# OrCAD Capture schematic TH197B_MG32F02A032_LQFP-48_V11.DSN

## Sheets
1 1. MLink: size B; title: MLink; rev: A; note: MLink
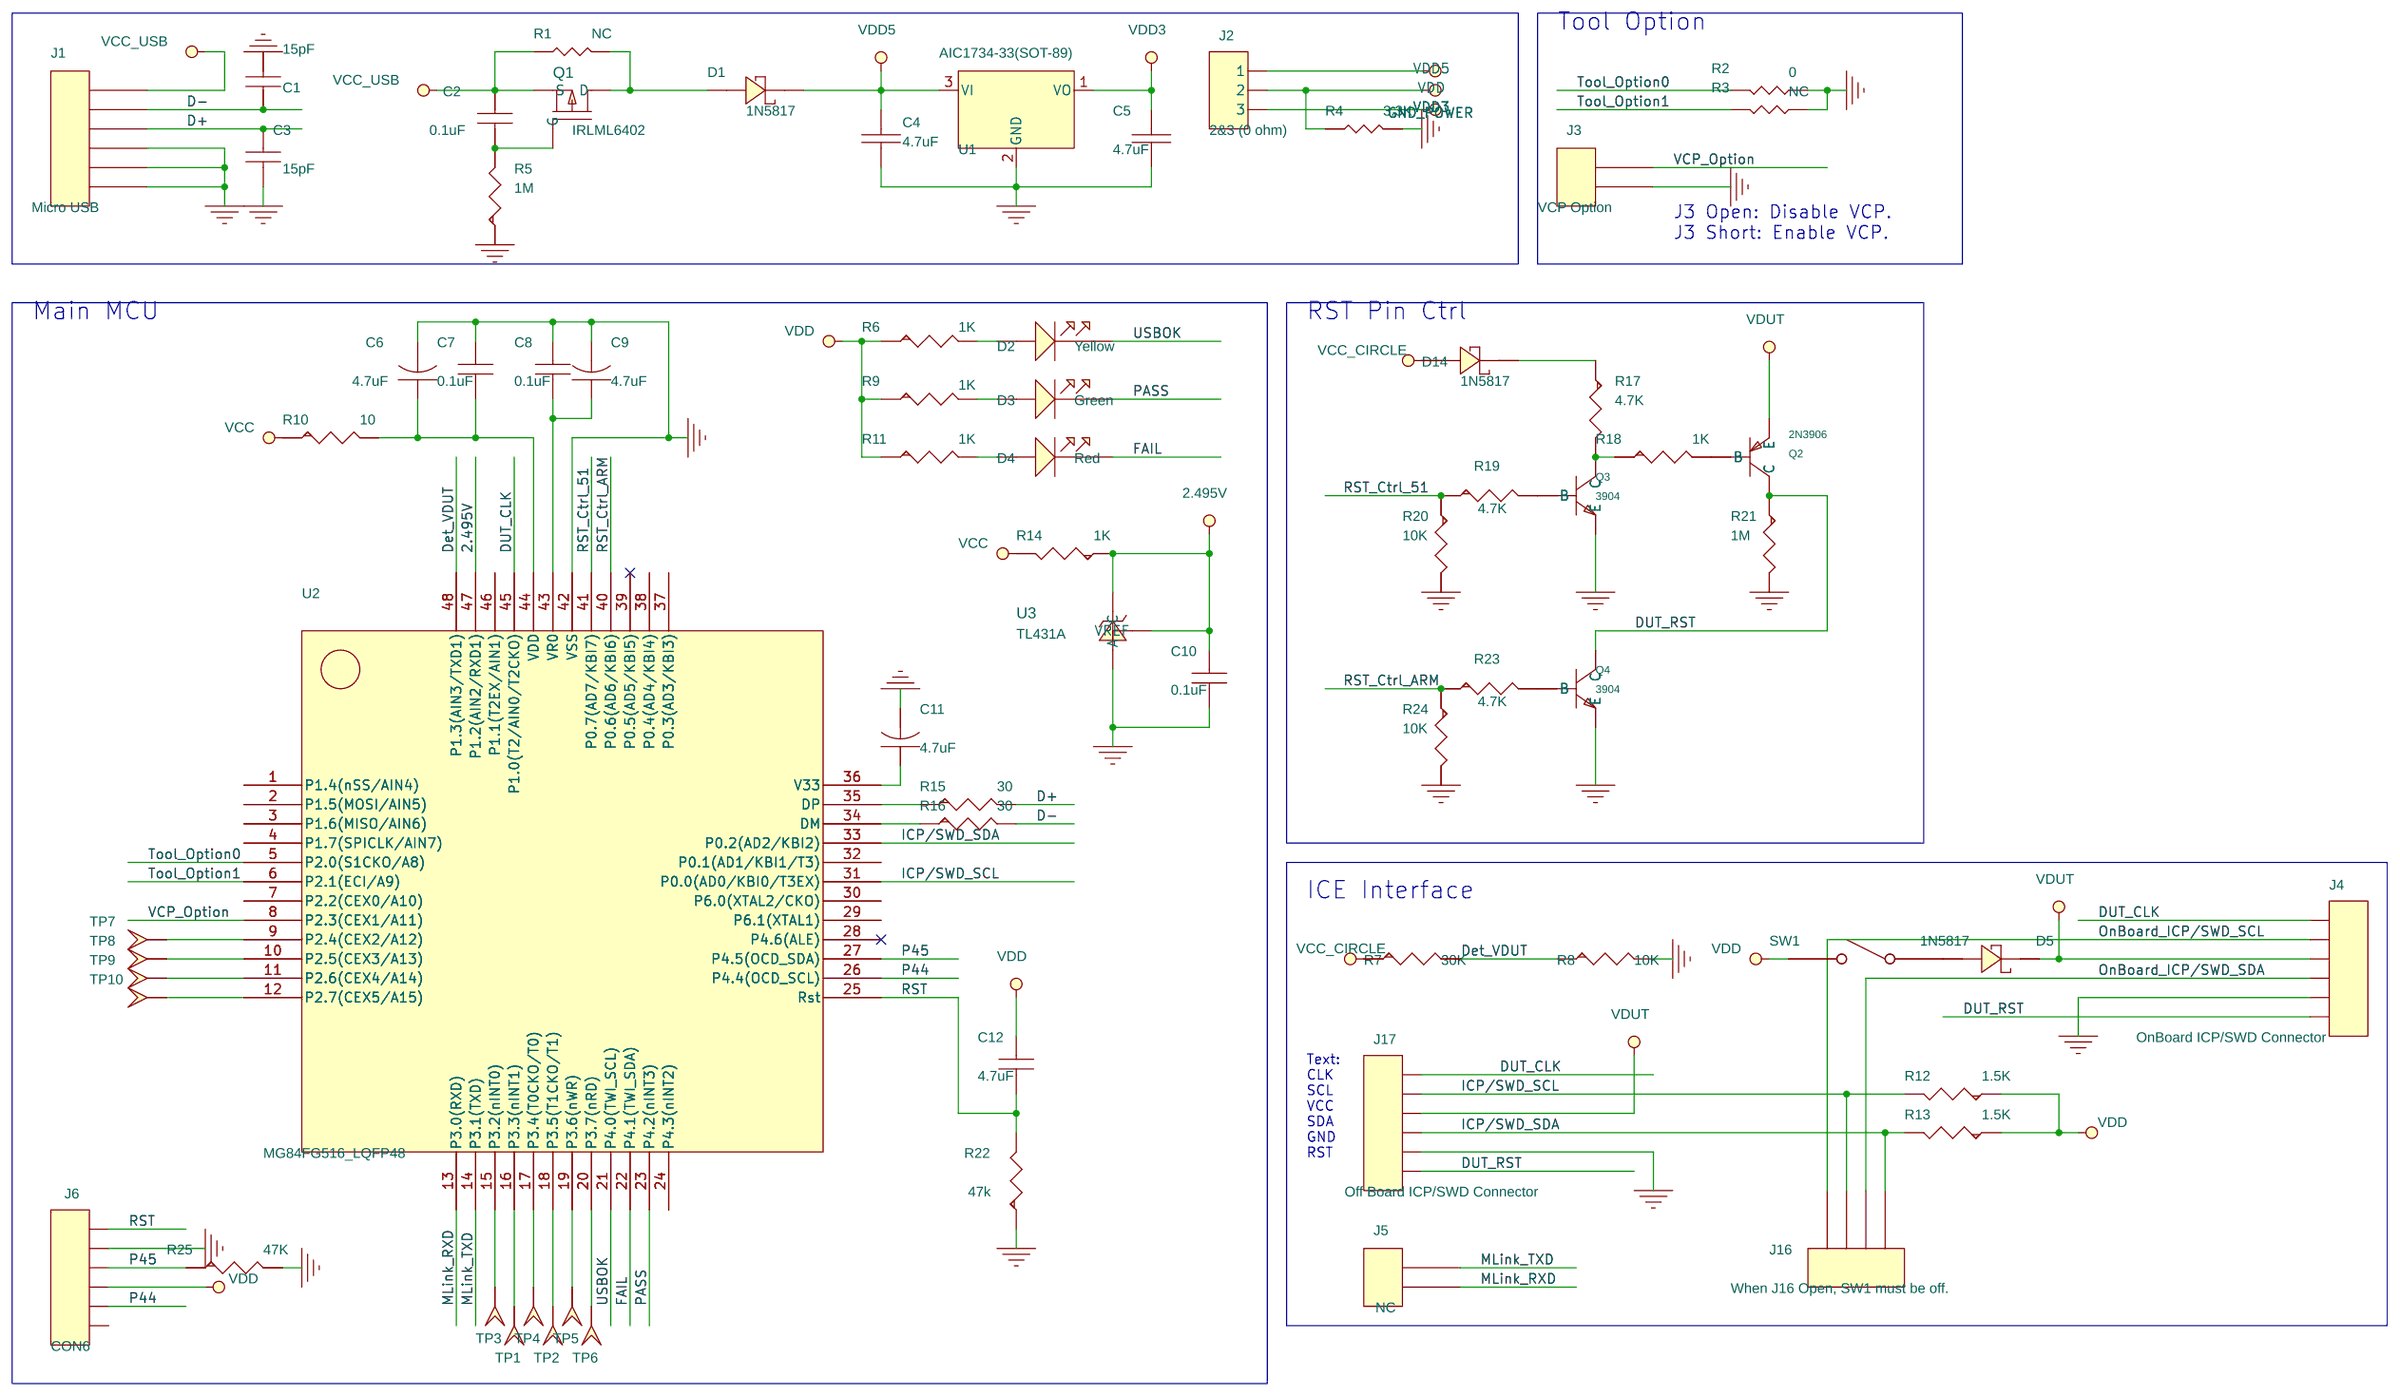
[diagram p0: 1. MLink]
2 2. MG32F02A032: size B; title: MG32F02A032_LQFP-48; note: MG32F02A032_LQFP-48
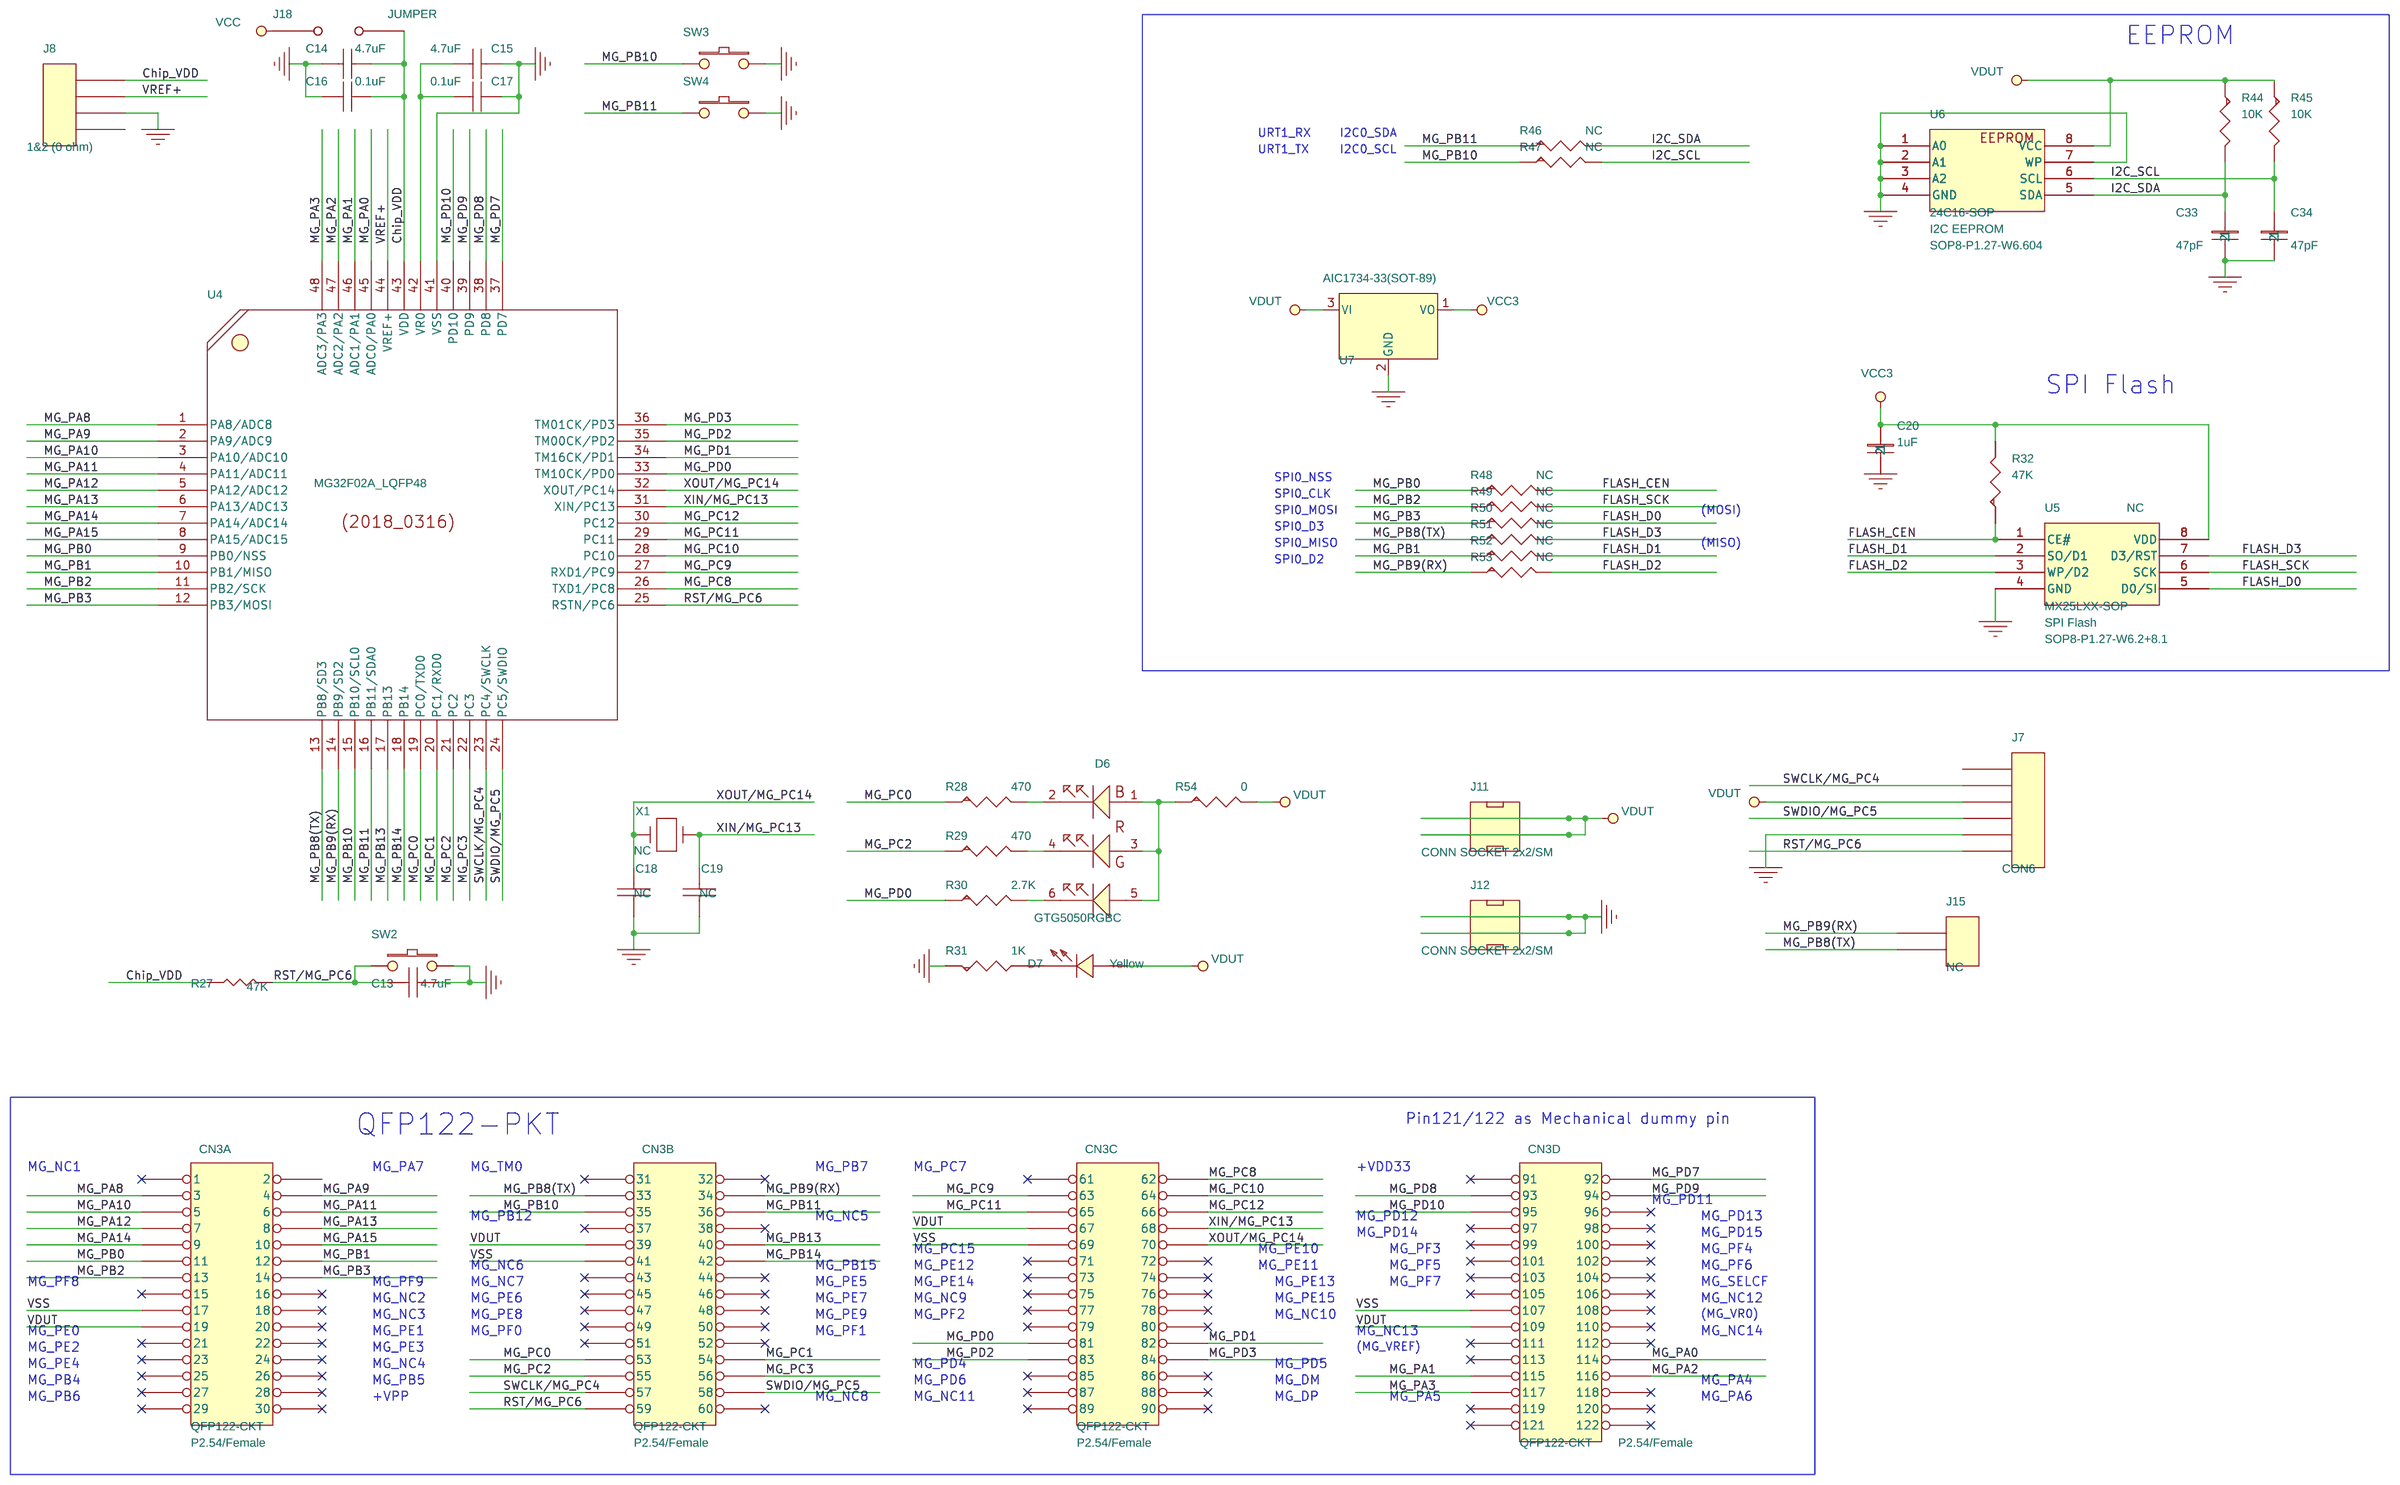
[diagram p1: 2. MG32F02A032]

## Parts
sheet 1. MLink
C1  15pF  [0805C]
C2  0.1uF  [0805C]
C3  15pF  [0805C]
C4  4.7uF  [1206C]
C5  4.7uF  [1206C]
C6  4.7uF  [0805C]
C7  0.1uF  [0805C]
C8  0.1uF  [0805C]
C9  4.7uF  [0805C]
C10  0.1uF  [0805C]
C11  4.7uF
C12  4.7uF  [C0805]
D1  1N5817  [D5817_SMD_1]
D2  Yellow  [0805D]
D3  Green  [0805D]
D4  Red  [0805D]
D5  1N5817  [D5817_SMD_1]
D14  1N5817  [D5817_SMD_1]
J1  Micro USB  [JACK_USB_SMD290X220P065]
J2  2&3 (0 ohm)
J3  VCP Option
J4  OnBoard ICP/SWD Connector
J5  NC
J6  CON6
J16  When J16 Open, SW1 must be off.
J17  Off Board ICP/SWD Connector
Q1  IRLML6402  [SOT23]
Q2  2N3906  [SOT23]
Q3  3904  [SOT23]
Q4  3904  [SOT23]
R1  NC  [0805R]
R2  0  [0805R]
R3  NC  [0805R]
R4  3.3K  [0805R]
R5  1M  [0805R]
R6  1K  [0805R]
R7  30K  [0805R]
R8  10K  [0805R]
R9  1K  [0805R]
R10  10  [0805R]
R11  1K  [0805R]
R12  1.5K  [0805R]
R13  1.5K  [0805R]
R14  1K  [0805R]
R15  30  [0805R]
R16  30  [0805R]
R17  4.7K  [0805R]
R18  1K  [0805R]
R19  4.7K  [0805R]
R20  10K  [0805R]
R21  1M  [0805R]
R22  47k  [0805R]
R23  4.7K  [0805R]
R24  10K  [0805R]
R25  47K  [0805R]
SW1  SW KEY-SPST  [DIP2_SW]
TP1  T POINT A
TP2  T POINT A
TP3  T POINT A
TP4  T POINT A
TP5  T POINT A
TP6  T POINT A
TP7  T POINT A
TP8  T POINT A
TP9  T POINT A
TP10  T POINT A
U1  AIC1734-33(SOT-89)  [SOT89]
U2  MG84FG516_LQFP48
U3  TL431A  [SOT23]
sheet 2. MG32F02A032
C13  4.7uF  [0805C]
C14  4.7uF  [0805C]
C15  4.7uF  [0805C]
C16  0.1uF  [0805C]
C17  0.1uF  [0805C]
C18  NC  [0805C]
C19  NC  [0805C]
C20  1uF  [C-0603]
C33  47pF  [C-0603]
C34  47pF  [C-0603]
CN3  QFP122-CKT  [QFP122-P2.54-CKT]  (sections A,B,C,D)
D6  GTG5050RGBC
D7  Yellow  [0805D]
J7  CON6  [PS6P254F_90]
J8  1&2 (0 ohm)  [PS4P254]
J11  CONN SOCKET 2x2/SM
J12  CONN SOCKET 2x2/SM
J15  NC
J18  JUMPER
R27  47K  [0805R]
R28  470  [0805R]
R29  470  [0805R]
R30  2.7K  [0805R]
R31  1K  [0805R]
R32  47K  [0805R]
R44  10K  [R-0603]
R45  10K  [R-0603]
R46  NC  [0805R]
R47  NC  [0805R]
R48  NC  [0805R]
R49  NC  [0805R]
R50  NC  [0805R]
R51  NC  [0805R]
R52  NC  [0805R]
R53  NC  [0805R]
R54  0  [0805R]
SW2  SW TACT-SPST
SW3  SW TACT-SPST
SW4  SW TACT-SPST
U4  MG32F02A_LQFP48  [LQFP48_7X7_050]
U5  MX25LXX-SOP  [SOP8-P1.27-W6.2+8.1]
U6  24C16-SOP  [SOP8-P1.27-W6.604]
U7  AIC1734-33(SOT-89)  [SOT89]
X1  NC  [X49U]

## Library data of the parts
C1-C3 C7 C8 C10 C12-C17 = CAP_NP
C4 C5 C18 C19 = C_NP
C6 C9 C11 = CAP
D1 D5 D14 = DIODE_SCHOTTKY
D2-D4 = Led0_0
J1 J7 = CON6_v2
J2 = CON3
J3 J5 J15 = CON2
J4 J6 J17 = CON6
J8 J16 = CON4
Q1 = MOSFET_P_GSD
Q2 = PNP_BEC
Q3 Q4 = NPN_BEC
R1-R4 R27 = R_v4
R5-R25 R28-R32 R46-R54 = R
SW1 = SW_KEY-SPST
TP1-TP10 = T_POINT_A
U1 U7 = AIC1722-33
U2 = MG84FG516_LQFP48
U3 = TL431_CYL
C20 = CAP-NP_1
C33 = CAP-NP_2: Package: C0603
C34 = CAP-NP: Package: C0603
CN3 = QFP122-CKT_2: Package: P2.54/Female
D6 = LED_GTG5050RGBC
D7 = LED
J11 J12 = CONN_SOCKET_2x2_SM
J18 = JUMPER
R44 R45 = R: 2ND PART FIELD: SMD_0805
SW2-SW4 = SW_TACT-SPST
U4 = IC-MG32F02A032-LQFP48
U5 = ICM-25LXX: Assembly: NC; Function: SPI Flash
U6 = ICM-24CXX: 1ST PART FIELD: OSD Record Buffer; 2ND PART FIELD: SOP_8PIN; Function: I2C EEPROM
X1 = CRYSTAL

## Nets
2.495V: C10.1 R14.1 U2.47(P1.2(AIN2/RXD1)) U3.1(VREF) U3.2(C)
GND_POWER: C1.2 C3.2 C4.2 C5.2 C6.2 C7.1 C8.1 C9.2 C10.2 C11.2 C13.1 C14.2 C15.2 C16.2 C17.2 C18.2 C19.2 C20.2 C33.2 C34.2 J1.4 J1.5 J1.6 J3.2 J4.5 J6.2 J7.5 J8.3 J12.1 J12.2 J12.3 J12.4 J17.5 Q3.2(E) Q4.2(E) R2.2 R3.2 R4.2 R5.1 R8.2 R20.2 R21.2 R22.1 R24.2 R25.2 R31.1 SW2.2 SW3.2 SW4.2 U1.2(GND) U2.42(VSS) U3.3(A) U4.41(VSS) U5.4(GND) U6.1(A0) U6.2(A1) U6.3(A2) U6.4(GND) U6.7(WP) U7.2(GND)
VCC3: C20.1 R32.2 U5.8(VDD) U7.1(VO)
VCC_USB: C2.1 D14.1(ANODE) J1.1 Q1.2(S) R1.1
VDD: C12.1 J2.2 J6.4 R4.1 R6.1 R9.1 R10.1 R11.1 R12.1 R13.1 R14.2 SW1.2
VDD3: C5.1 J2.3 U1.1(VO)
VDD5: C4.1 D1.2(CATHODE) J2.1 U1.3(VI)
VSS: CN3.17 CN3.41 CN3.69 CN3.107
Chip_VDD: C14.1 C16.1 J8.1 J18.2 R27.1 U4.43(VDD)
D+: C3.1 J1.3 R15.2
D-: C1.1 J1.2 R16.2
Det_VDUT: R7.2 R8.1 U2.48(P1.3(AIN3/TXD1))
DUT_CLK: J4.1 J17.1 U2.45(P1.0(T2/AIN0/T2CKO))
DUT_RST: J4.6 J17.6 Q2.3(C) Q4.3(C) R21.1
FAIL: D4.1 U2.22(P4.1(TWI_SDA))
FLASH_CEN: R32.1 R48.2 U5.1(CE#)
FLASH_D0: R50.2 U5.5(D0/SI)
FLASH_D1: R52.2 U5.2(SO/D1)
FLASH_D2: R53.2 U5.3(WP/D2)
FLASH_D3: R51.2 U5.7(D3/RST)
FLASH_SCK: R49.2 U5.6(SCK)
I2C_SCL: C34.1 R45.2 R47.2 U6.6(SCL)
I2C_SDA: C33.1 R44.2 R46.2 U6.5(SDA)
ICP/SWD_SCL: J16.2 J17.2 R12.2 U2.31(P0.0(AD0/KBI0/T3EX))
ICP/SWD_SDA: J16.4 J17.4 R13.2 U2.33(P0.2(AD2/KBI2))
MG_PA0: CN3.114 U4.45(ADC0/PA0)
MG_PA1: CN3.115 U4.46(ADC1/PA1)
MG_PA2: CN3.116 U4.47(ADC2/PA2)
MG_PA3: CN3.117 U4.48(ADC3/PA3)
MG_PA8: CN3.3 U4.1(PA8/ADC8)
MG_PA9: CN3.4 U4.2(PA9/ADC9)
MG_PA10: CN3.5 U4.3(PA10/ADC10)
MG_PA11: CN3.6 U4.4(PA11/ADC11)
MG_PA12: CN3.7 U4.5(PA12/ADC12)
MG_PA13: CN3.8 U4.6(PA13/ADC13)
MG_PA14: CN3.9 U4.7(PA14/ADC14)
MG_PA15: CN3.10 U4.8(PA15/ADC15)
MG_PB0: CN3.11 R48.1 U4.9(PB0/NSS)
MG_PB1: CN3.12 R52.1 U4.10(PB1/MISO)
MG_PB2: CN3.13 R49.1 U4.11(PB2/SCK)
MG_PB3: CN3.14 R50.1 U4.12(PB3/MOSI)
MG_PB8(TX): CN3.33 J15.2 R51.1 U4.13(PB8/SD3)
MG_PB9(RX): CN3.34 J15.1 R53.1 U4.14(PB9/SD2)
MG_PB10: CN3.35 R47.1 SW3.1 U4.15(PB10/SCL0)
MG_PB11: CN3.36 R46.1 SW4.1 U4.16(PB11/SDA0)
MG_PB13: CN3.40 U4.17(PB13)
MG_PB14: CN3.42 U4.18(PB14)
MG_PC0: CN3.53 R28.1 U4.19(PC0/TXD0)
MG_PC1: CN3.54 U4.20(PC1/RXD0)
MG_PC2: CN3.55 R29.1 U4.21(PC2)
MG_PC3: CN3.56 U4.22(PC3)
MG_PC8: CN3.62 U4.26(TXD1/PC8)
MG_PC9: CN3.63 U4.27(RXD1/PC9)
MG_PC10: CN3.64 U4.28(PC10)
MG_PC11: CN3.65 U4.29(PC11)
MG_PC12: CN3.66 U4.30(PC12)
MG_PD0: CN3.81 R30.1 U4.33(TM10CK/PD0)
MG_PD1: CN3.82 U4.34(TM16CK/PD1)
MG_PD2: CN3.83 U4.35(TM00CK/PD2)
MG_PD3: CN3.84 U4.36(TM01CK/PD3)
MG_PD7: CN3.92 U4.37(PD7)
MG_PD8: CN3.93 U4.38(PD8)
MG_PD9: CN3.94 U4.39(PD9)
MG_PD10: CN3.95 U4.40(PD10)
MLink_RXD: J5.2 U2.13(P3.0(RXD))
MLink_TXD: J5.1 U2.14(P3.1(TXD))
OnBoard_ICP/SWD_SCL: J4.2 J16.1
OnBoard_ICP/SWD_SDA: J4.4 J16.3
P44: J6.5 U2.26(P4.4(OCD_SCL))
P45: J6.3 R25.1 U2.27(P4.5(OCD_SDA))
PASS: D3.1 U2.23(P4.2(nINT3))
RST: C12.2 J6.1 R22.2 U2.25(Rst)
RST/MG_PC6: C13.2 CN3.59 J7.6 R27.2 SW2.1 U4.25(RSTN/PC6)
RST_Ctrl_51: R19.1 R20.1 U2.41(P0.7(AD7/KBI7))
RST_Ctrl_ARM: R23.1 R24.1 U2.40(P0.6(AD6/KBI6))
SWCLK/MG_PC4: CN3.57 J7.2 U4.23(PC4/SWCLK)
SWDIO/MG_PC5: CN3.58 J7.4 U4.24(PC5/SWDIO)
Tool_Option0: R2.1 U2.5(P2.0(S1CKO/A8))
Tool_Option1: R3.1 U2.6(P2.1(ECI/A9))
USBOK: D2.1 U2.21(P4.0(TWI_SCL))
VCP_Option: J3.1 U2.8(P2.3(CEX1/A11))
VDUT: CN3.19 CN3.39 CN3.67 CN3.109 D5.2(CATHODE) D7.1(ANODE) J4.3 J7.3 J11.1 J11.2 J11.3 J11.4 J17.3 J18.1 Q2.2(E) R7.1 R44.1 R45.1 R54.2 U6.8(VCC) U7.3(VI)
VREF+: J8.2 U4.44(VREF+)
XIN/MG_PC13: C19.1 CN3.68 U4.31(XIN/PC13) X1.2
XOUT/MG_PC14: C18.1 CN3.70 U4.32(XOUT/PC14) X1.1
N8265460: D6.1 D6.3 D6.5 R54.1
N8265636: C15.1 C17.1 U4.42(VR0)
N8274622: C8.2 C9.1 U2.43(VR0)
N8274678: C6.1 C7.2 R10.2 U2.44(VDD)
N8276034: C2.2 Q1.1(G) R5.2
N8276230: D2.2 R6.2
N8276234: D3.2 R9.2
N8276254: D4.2 R11.2
N8276368: D1.1(ANODE) Q1.3(D) R1.2
N8276836: TP1.1(TP) U2.16(P3.3(nINT1))
N8276840: TP2.1(TP) U2.18(P3.5(T1CKO/T1))
N8276924: R15.1 U2.35(DP)
N8276928: R16.1 U2.34(DM)
N8276948: C11.1 U2.36(V33)
N8290372: Q3.3(C) R17.2 R18.1
N8299254: D6.2 R28.2
N8299256: D6.4 R29.2
N8299258: D6.6 R30.2
N8326724: D5.1(ANODE) SW1.1
N8328150: D7.2(CATHODE) R31.2
N8343787: TP3.1(TP) U2.15(P3.2(nINT0))
N8343791: TP4.1(TP) U2.17(P3.4(T0CKO/T0))
N8343795: TP5.1(TP) U2.19(P3.6(nWR))
N8343799: TP6.1(TP) U2.20(P3.7(nRD))
N8343875: TP7.1(TP) U2.9(P2.4(CEX2/A12))
N8343881: TP8.1(TP) U2.10(P2.5(CEX3/A13))
N8343887: TP9.1(TP) U2.11(P2.6(CEX4/A14))
N8343893: TP10.1(TP) U2.12(P2.7(CEX5/A15))
N8346295: Q2.1(B) R18.2
N8346467: Q4.1(B) R23.2
N8346632: Q3.1(B) R19.2
N8351362: D14.2(CATHODE) R17.1

Not connected (* = marked no-connect by the designer): CN3 1* 2 15* 16* 18* 20* 21* 22* 23* 24* 25* 26* 27* 28* 29* 30* 31* 32* 37* 38* 43* 44* 45* 46* 47* 48* 49* 50* 51* 52* 60* 61* 71* 72* 73* 74* 75* 76* 77* 78* 79* 80* 85* 86* 87* 88* 89* 90* 91* 96* 97* 98* 99* 100* 101* 102* 103* 104* 105* 106* 108* 110* 111* 112* 113* 118* 119* 120* 121* 122*; J6 6; J7 1; J8 4; U2 1(P1.4(nSS/AIN4)) 2(P1.5(MOSI/AIN5)) 3(P1.6(MISO/AIN6)) 4(P1.7(SPICLK/AIN7)) 7(P2.2(CEX0/A10)) 24(P4.3(nINT2)) 28(P4.6(ALE))* 29(P6.1(XTAL1)) 30(P6.0(XTAL2/CKO)) 32(P0.1(AD1/KBI1/T3)) 37(P0.3(AD3/KBI3)) 38(P0.4(AD4/KBI4)) 39(P0.5(AD5/KBI5))* 46(P1.1(T2EX/AIN1))

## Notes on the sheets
sheet 1
- Tool Option
- J3 Open: Disable VCP.
  J3 Short: Enable VCP.
- Main MCU
- RST Pin Ctrl
- ICE Interface
- Text:
  CLK
  SCL
  VCC
  SDA
  GND
  RST
sheet 2
- EEPROM
- URT1_RX
- I2C0_SDA
- URT1_TX
- I2C0_SCL
- SPI Flash
- SPI0_CLK
- SPI0_NSS
- SPI0_MOSI
- (MOSI)
- SPI0_D3
- SPI0_MISO
- (MISO)
- SPI0_D2
- QFP122-PKT
- Pin121/122 as Mechanical dummy pin
- MG_NC1
- MG_PA7
- MG_TM0
- MG_PB7
- MG_PC7
- +VDD33
- MG_PD11
- MG_PB12
- MG_NC5
- MG_PD12
- MG_PD13
- MG_PC15
- MG_PE10
- MG_PD14
- MG_PF3
- MG_PD15
- MG_PF4
- MG_NC6
- MG_PB15
- MG_PE12
- MG_PE11
- MG_PF5
- MG_PF6
- MG_PF8
- MG_PF9
- MG_NC7
- MG_PE5
- MG_PE14
- MG_PE13
- MG_PF7
- MG_SELCF
- MG_NC2
- MG_PE6
- MG_PE7
- MG_NC9
- MG_PE15
- MG_NC12
- MG_NC3
- MG_PE8
- MG_PE9
- MG_PF2
- MG_NC10
- (MG_VR0)
- MG_PE0
- MG_PE1
- MG_PF0
- MG_PF1
- MG_NC13
- MG_NC14
- MG_PE2
- MG_PE4
- MG_NC4
- MG_PE3
- MG_PD4
- MG_PD5
- (MG_VREF)
- MG_PB4
- MG_PB5
- MG_PD6
- MG_DM
- MG_PA4
- MG_PB6
- +VPP
- MG_NC8
- MG_NC11
- MG_DP
- MG_PA5
- MG_PA6
